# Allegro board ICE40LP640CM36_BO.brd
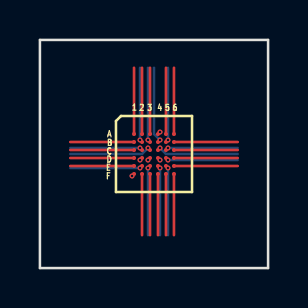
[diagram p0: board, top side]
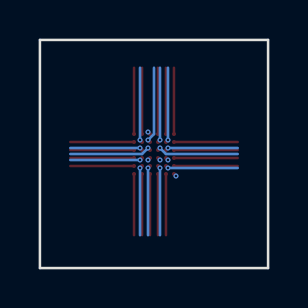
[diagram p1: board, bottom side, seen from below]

Outline 11.43 x 11.43 mm; copper layers: TOP, L2_GND, L3_PWR, BOTTOM. Coordinates in mm from the lower left corner of the outline.
Outline path: 0,11.43 0,0 11.43,0 11.43,11.43 0,11.43

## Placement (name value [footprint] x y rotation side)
U1  -  [CM36]  5.71 5.71 0 top

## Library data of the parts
U1 = CM36

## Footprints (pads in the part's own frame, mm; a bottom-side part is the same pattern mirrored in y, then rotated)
CM36
  round 0.2 smd: A1(-1,1) A2(-0.6,1) A3(-0.2,1) A4(0.2,1) A5(0.6,1) A6(1,1) B1(-1,0.6) B2(-0.6,0.6) B3(-0.2,0.6) B4(0.2,0.6) B5(0.6,0.6) B6(1,0.6) C1(-1,0.2) C2(-0.6,0.2) C3(-0.2,0.2) C4(0.2,0.2) C5(0.6,0.2) C6(1,0.2) D1(-1,-0.2) D2(-0.6,-0.2) D3(-0.2,-0.2) D4(0.2,-0.2) D5(0.6,-0.2) D6(1,-0.2) E1(-1,-0.6) E2(-0.6,-0.6) E3(-0.2,-0.6) E4(0.2,-0.6) E5(0.6,-0.6) E6(1,-0.6) F1(-1,-1) F2(-0.6,-1) F3(-0.2,-1) F4(0.2,-1) F5(0.6,-1) F6(1,-1)

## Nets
GND: U1.D2 U1.D3 U1.D4
VCC: U1.B2
CDONE_C4: U1.C4
CRESET_B_F4: U1.F4
GBIN0/PIO0_B3: U1.B3
GBIN1/PIO0_A3: U1.A3
GBIN2/PIO1_B4: U1.B4
GBIN3/PIO1_C5: U1.C5
GBIN5/PIO2_F2: U1.F2
GBIN6/PIO3/DP06A_D1: U1.D1
GBIN7/PIO3/DP05B_C1: U1.C1
PIO0_A2: U1.A2
PIO0_C3: U1.C3
PIO1_B5: U1.B5
PIO1_B6: U1.B6
PIO1_C6: U1.C6
PIO1_D6: U1.D6
PIO1_E6: U1.E6
PIO2/CBSEL0_E3: U1.E3
PIO2/CBSEL1_F3: U1.F3
PIO2_E2: U1.E2
PIO3/DP01A_B1: U1.B1
PIO3/DP01B_A1: U1.A1
PIO3/DP05A_C2: U1.C2
PIO3/DP06B_E1: U1.E1
PIOS/SPI_SCK_E5: U1.E5
PIOS/SPI_SI_F5: U1.F5
PIOS/SPI_SO_E4: U1.E4
PIOS/SPI_SS_B_D5: U1.D5
SPI_VCC_F6: U1.F6
VCCIO_0/1_A4: U1.A4
VCCIO_2/3_F1: U1.F1
VPP_2V5_A6: U1.A6
VPP_FAST_A5: U1.A5

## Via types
v1: diameter 0.254, hole 0.127, TOP to BOTTOM, 18 vias

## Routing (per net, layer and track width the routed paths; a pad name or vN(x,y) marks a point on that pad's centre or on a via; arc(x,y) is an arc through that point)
GND: length 0.4
  TOP w0.127: U1.D3 v1(5.42,5.42) ; U1.D4 v1(6.01,5.42) ; U1.D2 v1(5.01,5.42)
VCC: length 3.8
  TOP w0.127: U1.B2 v1(5.01,6.42)
  BOTTOM w0.127: v1(5.01,6.42) 5.01,10.03
CDONE_C4: length 4.2
  TOP w0.127: U1.C4 v1(6.01,6.01)
  BOTTOM w0.127: v1(6.01,6.01) 6.31,5.71 9.91,5.71
CRESET_B_F4: length 3.1
  TOP w0.127: U1.F4 5.91,1.65
GBIN0/PIO0_B3: length 3.8
  TOP w0.127: U1.B3 v1(5.42,6.42)
  BOTTOM w0.127: v1(5.42,6.42) 5.42,10.03
GBIN1/PIO0_A3: length 3.3
  TOP w0.127: U1.A3 5.52,10.03
GBIN2/PIO1_B4: length 3.9
  TOP w0.127: U1.B4 v1(6.01,6.42)
  BOTTOM w0.127: v1(6.01,6.42) 5.71,6.71 5.71,10.03
GBIN3/PIO1_C5: length 3.6
  TOP w0.127: U1.C5 v1(6.42,6.01)
  BOTTOM w0.127: v1(6.42,6.01) 9.91,6.01
GBIN5/PIO2_F2: length 3.1
  TOP w0.127: U1.F2 5.12,1.65
GBIN6/PIO3/DP06A_D1: length 3.2
  TOP w0.127: U1.D1 1.52,5.52
GBIN7/PIO3/DP05B_C1: length 3.2
  TOP w0.127: U1.C1 1.52,5.91
PIO0_A2: length 3.3
  TOP w0.127: U1.A2 5.12,10.03
PIO0_C3: length 4.2
  TOP w0.127: U1.C3 v1(5.42,6.01)
  BOTTOM w0.127: 1.52,5.71 5.12,5.71 v1(5.42,6.01)
PIO1_B5: length 3.8
  TOP w0.127: U1.B5 v1(6.42,6.42)
  BOTTOM w0.127: v1(6.42,6.42) 6.42,10.03
PIO1_B6: length 3.2
  TOP w0.127: U1.B6 9.91,6.31
PIO1_C6: length 3.2
  TOP w0.127: U1.C6 9.91,5.91
PIO1_D6: length 3.2
  TOP w0.127: U1.D6 9.91,5.52
PIO1_E6: length 3.2
  TOP w0.127: U1.E6 9.91,5.12
PIO2/CBSEL0_E3: length 3.5
  TOP w0.127: U1.E3 v1(5.42,5.01)
  BOTTOM w0.127: v1(5.42,5.01) 5.42,1.65
PIO2/CBSEL1_F3: length 3.1
  TOP w0.127: U1.F3 5.52,1.65
PIO2_E2: length 3.6
  TOP w0.127: U1.E2 v1(5.01,5.01)
  BOTTOM w0.127: v1(5.01,5.01) 1.52,5.01
PIO3/DP01A_B1: length 3.2
  TOP w0.127: U1.B1 1.52,6.31
PIO3/DP01B_A1: length 3.3
  TOP w0.127: U1.A1 4.72,10.03
PIO3/DP05A_C2: length 3.6
  TOP w0.127: U1.C2 v1(5.01,6.01)
  BOTTOM w0.127: v1(5.01,6.01) 1.52,6.01
PIO3/DP06B_E1: length 3.2
  TOP w0.127: U1.E1 1.52,5.12
PIOS/SPI_SCK_E5: length 3.5
  TOP w0.127: U1.E5 v1(6.42,5.01)
  BOTTOM w0.127: v1(6.42,5.01) 6.42,1.65
PIOS/SPI_SI_F5: length 3.1
  TOP w0.127: U1.F5 6.31,1.65
PIOS/SPI_SO_E4: length 3.5
  TOP w0.127: U1.E4 v1(6.01,5.01)
  BOTTOM w0.127: v1(6.01,5.01) 6.01,1.65
PIOS/SPI_SS_B_D5: length 3.6
  TOP w0.127: U1.D5 v1(6.42,5.42)
  BOTTOM w0.127: v1(6.42,5.42) 9.91,5.42
SPI_VCC_F6: length 3.1
  TOP w0.127: U1.F6 6.71,1.65
VCCIO_0/1_A4: length 0.1
  TOP w0.127: U1.A4 v1(6.01,6.82)
VCCIO_2/3_F1: length 0.1
  TOP w0.127: U1.F1 v1(4.61,4.61)
VPP_2V5_A6: length 3.3
  TOP w0.127: U1.A6 6.71,10.03
VPP_FAST_A5: length 3.3
  TOP w0.127: U1.A5 6.31,10.03

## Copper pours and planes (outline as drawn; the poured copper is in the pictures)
GND on L2_GND: 1.27,10.16 10.16,10.16 10.16,1.27 1.27,1.27
VCCIO_0/1_A4 on L3_PWR: 4.95,7.62 4.95,6.48 5.21,6.48 5.21,5.97 6.1,5.97 6.1,3.81 7.62,3.81 7.62,7.62
VCCIO_2/3_F1 on L3_PWR: 3.81,7.62 3.81,3.81 5.97,3.81 5.97,5.84 4.95,5.84 4.95,6.35 4.83,6.35 4.83,7.62

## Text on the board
Ref Des/Silkscreen Top: BGA Pad = 7.87 Mils | BGA Pad Soldermask = 13.39 Mils | BGA Via = 10 Mils Pad | BGA Tracks = 5 Mils Width | 5 Mils Drill | 3.5 Mils spacing.
LEGEND: 26-JUNE-2012
NCLEGEND-1-4: FIGURE | SIZE | 5.0 | DRILL CHART: TOP to BOTTOM | ALL UNITS ARE IN MILS | PLATED | QTY | 18
User.11: DRILL DRAWING
User.12: TOP LAYER
User.13: BOTTOM LAYER
User.14: L2-GND LAYER
User.15: L3-PWR LAYER
User.16: SILKSCREEN TOP
User.17: SOLDERMASK TOP
User.18: PASTEMASK TOP
User.20: 1.Specifications: | 6.2 Registration to be +/- .005" and must pass peel test. | 7.2 Electrical test report (BBT) is to be provided along with PCB's. | 12.0 PCB's are to confirm to IPC-A-600D standards. | 3.Soldermask: | 3.0 Soldermask both sides with (green color) liquid photoimageble soldermask | 8.Cleanlines: | 1.0 Producibility study- it is the responsibility of the supplier to conduct | 1.1 This drawing is to be used in conjuction with the provided gerber and | 2.Material: | 2.0 NEMA Grade FR-4/Epoxy class , foil lamination structure for core and | 2.1 Color is vendor's option. | 6.Silkscreen: | 6.0 Silksceen using white non-conductive epoxy or equivalent ( both sides ). | 6.1 No Silkscreen allowed on exposed lands or in holes (burnout with soldermask) | 7.Electrical Test: | 7.0 All boards shall be 100% elecrically tested for open/shorts. | 7.1 Apply test stamp in non legend area on the solder side of PCB. | 8.0 Boards shall be free of fiber glass dust or any other forgien material. | 8.1 Finished boards must conform to 0.01 MG/IN max NAcl ionic contamonation | 9.Packaging: | 9.0 There shall be max of 25 units per package wrapped in sulpher and silicone | 10.Bow and Twist: | 10.0 Bow and twist to be .007" per Inch or .090 max according to IPC-A-600D. | 11.Inspection: | 11.0 Automatic optical inspection of all layers is required. | 4. Drilling: | 4.0 All hole diameters are finished sizes. | 4.1 All holes to be +/- .003" from the true postion unless otherwise specified. | 4.2 All holes diameters to be +/- .003" unless otherwise specified. | 4.3 An CNC drill file has been supplied - see drill table. | 5.Finish: | 5.0 Plate thru with copper .001" min to .002" max thickness drill size. | 5.1 Solder dip and hot air level with 63/37% tin/lead cpating, .0002" min to | 5.2 Finished boards shall not have nicks, scratches, voids, exposed copper, | thorough review of the artwork and media for manufacturablity in the | supplier's process compliance to all applicable specifications. The | customer must be advised in writing (inadvance of manufacturing) of any | changes, revisions, or corrections made or recommendations to ensure | conformance to the customers standards, and of any specifications that | cannot met. | drill data where applicable. | copper thickness: type GFN, Grade A, Class 1, Class A. | as measured bu omega meter 600SMD. | free material and contained in heavy cardboard cartons with sufficient | surrounding material to prevent shipping damage. | .003 max. thickness. Soldermask over bare copper. | dimensions apply after plating. | .001" max. | poor plating, or misdrilled holes. | General Instructions: | 4. Impedance Requirements: | 4.a. All tracks with 0.3mm (0.15 neck in BGA areas) in all layers, | 4.b. Please adjust the tracks width or stack to achieve this. | 5. PCB thickness: 1.6 mm or as per order or as dictated by Impedance. | 1. All instructions mentioned herein overrides | 2. Instructions in purchase order also overrides | 3. Incase of any clarifications or contradicting instructions, | general instructions. | Please call or mail: | Company: Manipal Dot Net Pvt Ltd., Manipal, INDIA. | Cell :   91-98452-43213 | e-mail : pcbinfo@manipal.net | are 50 Ohms, single ended. | TOP SIDE    - LAYER 1  SIGNAL LAYER | L2-GND PLANE   - LAYER 2  1 OZ. CU. | L3-PWR PLANE   - LAYER 3 1 OZ. CU. | BOTTOM SIDE - LAYER 4 SIGNAL LAYER | Board specific Instructions:
